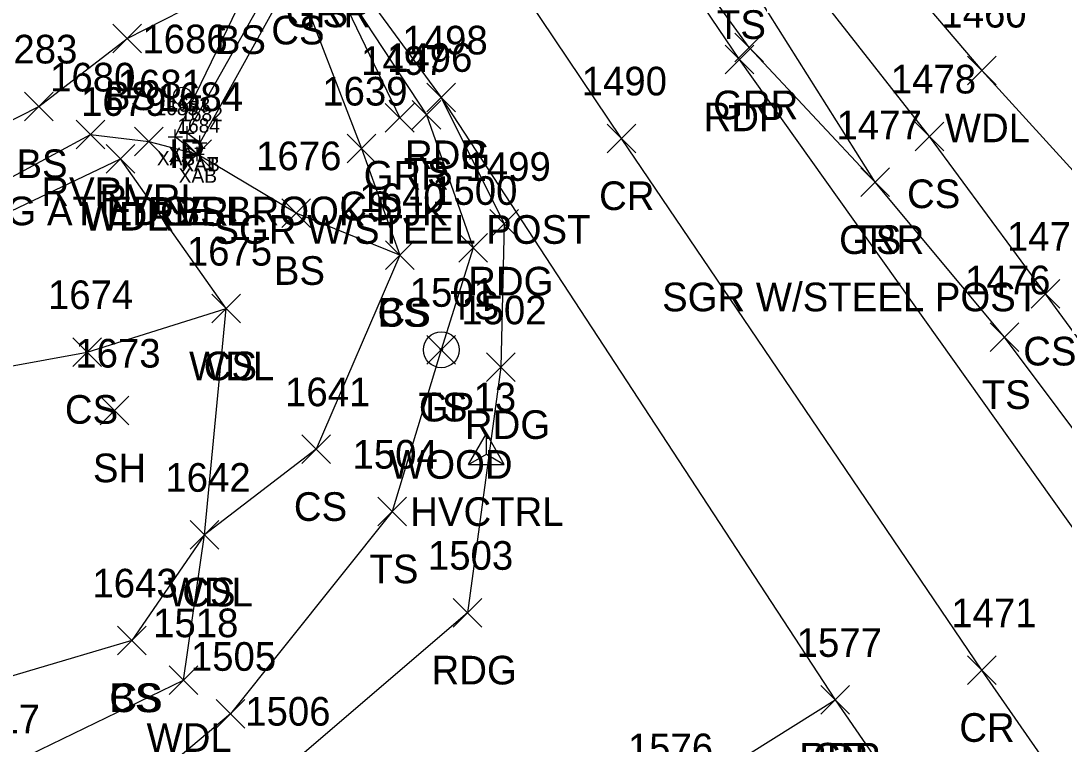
# Model space of a CAD drawing. Extents: x 1501299 to 1502485, y 381423 to 383765.
# Drawn here: x 1501597.6 to 1501670.4, y 383226.1 to 383276.5 of the extents above; entities that cross this region are included whole.
import ezdxf

# ---------------------------------------------------------------- set-up
doc = ezdxf.new("R2010")
doc.units = 0
for name, color, linetype in [('B_A', 7, 'Continuous'), ('B_I', 7, 'Continuous'), ('B_TIC', 7, 'Continuous'), ('BSUBM', 7, 'Continuous'), ('C_A', 7, 'Continuous'), ('C_I', 7, 'Continuous'), ('CPSM', 7, 'Continuous'), ('L_A', 7, 'Continuous'), ('L_C', 7, 'Continuous'), ('L_I', 7, 'Continuous'), ('L_TIC', 7, 'Continuous'), ('LAWA', 7, 'Continuous'), ('LAWE', 7, 'Continuous'), ('LELB', 7, 'Continuous'), ('M_A', 7, 'Continuous'), ('M_C', 7, 'Continuous'), ('M_I', 7, 'Continuous'), ('MPIR', 7, 'Continuous'), ('P_A', 7, 'Continuous'), ('P_I', 7, 'Continuous'), ('P_TIC', 7, 'Continuous'), ('PET', 7, 'Continuous'), ('PEU', 7, 'Continuous'), ('PRC', 7, 'Continuous'), ('R_A', 7, 'Continuous'), ('R_C', 7, 'Continuous'), ('R_I', 7, 'Continuous'), ('R_TIC', 7, 'Continuous'), ('RGP', 7, 'Continuous'), ('RGR', 7, 'Continuous')]:
    doc.layers.add(name, color=color, linetype=linetype)

msp = doc.modelspace()

# ---------------------------------------------------------------- linework, layer by layer
at = {"layer": 'B_TIC'}
for p, q in [((1501608.386, 383268.462), (1501608.461, 383268.462)), ((1501609.222, 383268.708), (1501609.297, 383268.708)), ((1501610.102, 383268.035), (1501610.177, 383268.035)), ((1501610.102, 383268.035), (1501610.177, 383268.035)), ((1501609.908, 383267.245), (1501609.984, 383267.245))]:
    msp.add_line(p, q, dxfattribs=at)
for points in [[(1501609.218, 383268.208), (1501609.218, 383269.208)], [(1501607.882, 383268.462), (1501608.882, 383268.462)], [(1501608.382, 383267.962), (1501608.382, 383268.962)], [(1501608.718, 383268.708), (1501609.718, 383268.708)], [(1501610.098, 383267.535), (1501610.098, 383268.535)], [(1501610.098, 383267.535), (1501610.098, 383268.535)], [(1501609.598, 383268.035), (1501610.598, 383268.035)], [(1501609.598, 383268.035), (1501610.598, 383268.035)], [(1501609.905, 383266.745), (1501609.905, 383267.745)], [(1501609.405, 383267.245), (1501610.405, 383267.245)]]:
    msp.add_lwpolyline(points, dxfattribs=at)
at = {"layer": 'BSUBM'}
for points in [[(1501610.098, 383268.035), (1501609.905, 383267.245), (1501608.382, 383268.462), (1501613.451, 383278.934), (1501614.534, 383280.635), (1501624.293, 383289.139), (1501630.288, 383293.913), (1501635.348, 383298.565), (1501649.431, 383296.917), (1501649.596, 383294.923)], [(1501617.009, 383280.262), (1501616.648, 383279.899), (1501610.098, 383268.035), (1501609.218, 383268.708), (1501615.801, 383280.376)]]:
    msp.add_lwpolyline(points, dxfattribs=at)
at = {"layer": 'CPSM'}
for p, q in [((1501628.837, 383245.579), (1501630.087, 383247.744)), ((1501631.337, 383245.579), (1501630.087, 383247.744)), ((1501630.087, 383246.3), (1501630.087, 383247.744)), ((1501628.837, 383245.579), (1501630.087, 383246.3)), ((1501630.087, 383246.3), (1501630.087, 383246.3)), ((1501630.087, 383246.3), (1501631.337, 383245.579)), ((1501628.837, 383245.579), (1501631.337, 383245.579))]:
    msp.add_line(p, q, dxfattribs=at)
at = {"layer": 'L_TIC'}
for points in [[(1501604.035, 383274.317), (1501606.035, 383276.317)], [(1501606.035, 383274.317), (1501604.035, 383276.317)], [(1501663.652, 383272.077), (1501665.652, 383274.077)], [(1501665.652, 383272.077), (1501663.652, 383274.077)], [(1501597.871, 383269.571), (1501599.871, 383271.571)], [(1501599.871, 383269.571), (1501597.871, 383271.571)], [(1501624.909, 383268.987), (1501626.909, 383270.987)], [(1501626.909, 383268.987), (1501624.909, 383270.987)], [(1501601.485, 383267.617), (1501603.485, 383269.617)], [(1501603.485, 383267.617), (1501601.485, 383269.617)], [(1501605.539, 383267.133), (1501607.539, 383269.133)], [(1501607.539, 383267.133), (1501605.539, 383269.133)], [(1501659.991, 383267.478), (1501661.991, 383269.478)], [(1501661.991, 383267.478), (1501659.991, 383269.478)], [(1501620.389, 383266.635), (1501622.389, 383268.635)], [(1501622.389, 383266.635), (1501620.389, 383268.635)], [(1501603.566, 383265.915), (1501605.566, 383267.915)], [(1501605.566, 383265.915), (1501603.566, 383267.915)], [(1501603.566, 383265.915), (1501605.566, 383267.915)], [(1501605.566, 383265.915), (1501603.566, 383267.915)], [(1501608.905, 383266.245), (1501610.905, 383268.245)], [(1501610.905, 383266.245), (1501608.905, 383268.245)], [(1501608.905, 383266.245), (1501610.905, 383268.245)], [(1501610.905, 383266.245), (1501608.905, 383268.245)], [(1501656.204, 383264.279), (1501658.204, 383266.279)], [(1501658.204, 383264.279), (1501656.204, 383266.279)], [(1501615.825, 383262.123), (1501617.825, 383264.123)], [(1501617.825, 383262.123), (1501615.825, 383264.123)], [(1501623.053, 383259.203), (1501625.053, 383261.203)], [(1501625.053, 383259.203), (1501623.053, 383261.203)], [(1501623.053, 383259.203), (1501625.053, 383261.203)], [(1501625.053, 383259.203), (1501623.053, 383261.203)], [(1501628.163, 383259.706), (1501630.163, 383261.706)], [(1501630.163, 383259.706), (1501628.163, 383261.706)], [(1501668.093, 383256.5), (1501670.093, 383258.5)], [(1501670.093, 383256.5), (1501668.093, 383258.5)], [(1501610.935, 383255.467), (1501612.935, 383257.467)], [(1501612.935, 383255.467), (1501610.935, 383257.467)], [(1501610.935, 383255.467), (1501612.935, 383257.467)], [(1501612.935, 383255.467), (1501610.935, 383257.467)], [(1501665.231, 383253.465), (1501667.231, 383255.465)], [(1501667.231, 383253.465), (1501665.231, 383255.465)], [(1501625.947, 383252.594), (1501627.947, 383254.594)], [(1501627.947, 383252.594), (1501625.947, 383254.594)], [(1501601.248, 383252.433), (1501603.248, 383254.433)], [(1501603.248, 383252.433), (1501601.248, 383254.433)], [(1501603.156, 383248.352), (1501605.156, 383250.352)], [(1501605.156, 383248.352), (1501603.156, 383250.352)], [(1501617.219, 383245.655), (1501619.219, 383247.655)], [(1501619.219, 383245.655), (1501617.219, 383247.655)], [(1501622.522, 383241.303), (1501624.522, 383243.303)], [(1501624.522, 383241.303), (1501622.522, 383243.303)], [(1501609.438, 383239.687), (1501611.438, 383241.687)], [(1501611.438, 383239.687), (1501609.438, 383241.687)], [(1501609.438, 383239.687), (1501611.438, 383241.687)], [(1501611.438, 383239.687), (1501609.438, 383241.687)], [(1501604.349, 383232.312), (1501606.349, 383234.312)], [(1501606.349, 383232.312), (1501604.349, 383234.312)], [(1501604.349, 383232.312), (1501606.349, 383234.312)], [(1501606.349, 383232.312), (1501604.349, 383234.312)], [(1501607.969, 383229.539), (1501609.969, 383231.539)], [(1501609.969, 383229.539), (1501607.969, 383231.539)], [(1501611.249, 383227.196), (1501613.249, 383229.196)], [(1501613.249, 383227.196), (1501611.249, 383229.196)]]:
    msp.add_lwpolyline(points, dxfattribs=at)
at = {"layer": 'LAWA'}
for points in [[(1501779.978, 383346.811), (1501771.128, 383336.509), (1501763.603, 383335.595), (1501745.623, 383331.34), (1501736.099, 383321.476), (1501724.597, 383316.37), (1501714.925, 383312.283), (1501706.399, 383305.205), (1501697.057, 383304.744), (1501686.727, 383299.314), (1501680.172, 383293.143), (1501673.639, 383291.799), (1501663.46, 383290.945), (1501650.482, 383288.163), (1501656.051, 383283.209), (1501664.652, 383273.077), (1501676.933, 383259.602)], [(1501523.121, 383213.314), (1501532.426, 383219.38), (1501535.216, 383227.124), (1501552.763, 383237.535), (1501565.994, 383247.177), (1501582.963, 383255.302), (1501593.872, 383261.815), (1501604.566, 383266.915)], [(1501528.627, 383177.649), (1501552.889, 383189.247), (1501565.057, 383199.711), (1501579.739, 383213.943), (1501595.135, 383223.841), (1501608.969, 383230.539), (1501610.438, 383240.687), (1501611.935, 383256.467), (1501604.566, 383266.915)]]:
    msp.add_lwpolyline(points, dxfattribs=at)
at = {"layer": 'LAWE'}
msp.add_lwpolyline([(1501505.158, 383203.166), (1501520.7, 383214.779), (1501528.923, 383219.093), (1501532.525, 383227.492), (1501551.851, 383239.1), (1501563.534, 383248.346), (1501581.909, 383257.47), (1501592.134, 383263.024), (1501602.485, 383268.617), (1501606.539, 383268.133), (1501609.905, 383267.245)], dxfattribs=at)
at = {"layer": 'LELB'}
for points in [[(1501590.761, 383266.457), (1501598.871, 383270.571), (1501605.035, 383275.317), (1501612.707, 383279.234), (1501613.789, 383281.85), (1501615.914, 383283.693), (1501614.455, 383284.683), (1501622.35, 383292.222), (1501627.416, 383296.435), (1501634.13, 383302.054), (1501643.772, 383300.983), (1501650.033, 383300.072), (1501651.493, 383297.792), (1501662.757, 383297.227), (1501671.557, 383298.422), (1501684.76, 383303.845), (1501698.893, 383313.194), (1501704.538, 383312.156), (1501711.847, 383316.203), (1501724.827, 383323.61), (1501744.215, 383336.813), (1501764.443, 383344.5)], [(1501740.606, 383142.674), (1501732.682, 383153.534), (1501723.163, 383169.564), (1501715.733, 383180.538), (1501695.363, 383208.817), (1501677.401, 383239.568), (1501666.231, 383254.465), (1501657.204, 383265.279), (1501647.762, 383280.285), (1501635.957, 383296.227)], [(1501736.699, 383153.056), (1501732.682, 383153.534), (1501726.373, 383172.274), (1501718.918, 383183.465), (1501700.045, 383211.098), (1501680.296, 383242.203), (1501669.093, 383257.5), (1501660.991, 383268.478), (1501649.565, 383283.093), (1501640.692, 383295.782)], [(1501619.162, 383281.8), (1501618.614, 383281.102), (1501625.909, 383269.987), (1501629.163, 383260.706), (1501626.947, 383253.594), (1501623.522, 383242.303), (1501612.249, 383228.196), (1501584.091, 383204.532), (1501565.556, 383192.677), (1501531.011, 383172.484)], [(1501616.648, 383279.899), (1501621.389, 383267.635), (1501624.053, 383260.203), (1501618.219, 383246.655), (1501610.438, 383240.687), (1501605.349, 383233.312)], [(1501624.053, 383260.203), (1501616.825, 383263.123), (1501609.905, 383267.245)], [(1501535.216, 383227.124), (1501558.161, 383232.007), (1501574.325, 383240.882), (1501582.487, 383249.817), (1501602.248, 383253.433), (1501611.935, 383256.467)], [(1501605.349, 383233.312), (1501590.603, 383228.948), (1501573.553, 383221.004), (1501565.086, 383213.343), (1501549.824, 383204.977), (1501532.49, 383198.66), (1501516.236, 383190.974)]]:
    msp.add_lwpolyline(points, dxfattribs=at)
at = {"layer": 'MPIR'}
for radius in [0.625, 0.0833]:
    msp.add_circle((1501608.89, 383271.282), radius, dxfattribs=at)
at = {"layer": 'P_TIC'}
for points in [[(1501646.754, 383272.845), (1501648.754, 383274.845)], [(1501648.754, 383272.845), (1501646.754, 383274.845)], [(1501625.926, 383270.201), (1501627.926, 383272.201)], [(1501627.926, 383270.201), (1501625.926, 383272.201)], [(1501625.926, 383270.201), (1501627.926, 383272.201)], [(1501627.926, 383270.201), (1501625.926, 383272.201)], [(1501638.517, 383267.342), (1501640.517, 383269.342)], [(1501640.517, 383267.342), (1501638.517, 383269.342)], [(1501630.334, 383261.382), (1501632.334, 383263.382)], [(1501632.334, 383261.382), (1501630.334, 383263.382)], [(1501630.108, 383251.373), (1501632.108, 383253.373)], [(1501632.108, 383251.373), (1501630.108, 383253.373)], [(1501627.782, 383234.244), (1501629.782, 383236.244)], [(1501629.782, 383234.244), (1501627.782, 383236.244)], [(1501663.644, 383230.239), (1501665.644, 383232.239)], [(1501665.644, 383230.239), (1501663.644, 383232.239)], [(1501653.425, 383228.168), (1501655.425, 383230.168)], [(1501655.425, 383228.168), (1501653.425, 383230.168)], [(1501653.425, 383228.168), (1501655.425, 383230.168)], [(1501655.425, 383228.168), (1501653.425, 383230.168)]]:
    msp.add_lwpolyline(points, dxfattribs=at)
at = {"layer": 'PET'}
msp.add_lwpolyline([(1501787.994, 383066.094), (1501768.484, 383096.751), (1501754.41, 383116.891), (1501736.241, 383144.717), (1501720.749, 383167.971), (1501712.594, 383179.719), (1501694.383, 383207.646), (1501673.597, 383237.523), (1501647.754, 383273.845), (1501633.679, 383294.635), (1501626.393, 383287.881), (1501619.162, 383281.8), (1501626.926, 383271.201), (1501654.425, 383229.168), (1501675.697, 383198.288), (1501696.699, 383166.339)], dxfattribs=at)
at = {"layer": 'PEU'}
msp.add_lwpolyline([(1501626.926, 383271.201), (1501631.334, 383262.382), (1501631.108, 383252.373), (1501628.782, 383235.244), (1501616.096, 383224.369), (1501585.575, 383201.963), (1501565.972, 383189.419), (1501531.444, 383171.521)], dxfattribs=at)
at = {"layer": 'PRC'}
for points in [[(1501960.612, 382718.648), (1501950.96, 382750.482), (1501934.965, 382791.852), (1501913.074, 382836.935), (1501889.309, 382881.383), (1501879.244, 382899.507), (1501856.391, 382940.32), (1501839.674, 382966.998), (1501816.055, 383004.313), (1501794.783, 383036.247), (1501769.812, 383075.158), (1501745.791, 383111.558), (1501729.435, 383136.001), (1501711.236, 383163.535), (1501694.816, 383188.199), (1501683.547, 383204.004), (1501664.644, 383231.239), (1501639.517, 383268.342), (1501626.393, 383287.881)], [(1501538.389, 383162.062), (1501572.089, 383180.105), (1501595.76, 383192.822), (1501620.625, 383207.907), (1501642.704, 383221.815), (1501654.425, 383229.168)]]:
    msp.add_lwpolyline(points, dxfattribs=at)
at = {"layer": 'R_TIC'}
for points in [[(1501647.418, 383273.675), (1501649.418, 383275.675)], [(1501649.418, 383273.675), (1501647.418, 383275.675)], [(1501623.041, 383268.773), (1501625.041, 383270.773)], [(1501625.041, 383268.773), (1501623.041, 383270.773)], [(1501656.204, 383264.279), (1501658.204, 383266.279)], [(1501658.204, 383264.279), (1501656.204, 383266.279)]]:
    msp.add_lwpolyline(points, dxfattribs=at)
at = {"layer": 'RGP'}
msp.add_line((1501626.947, 383253.594), (1501626.947, 383253.594), dxfattribs=at)
for radius in [1.25, 0.0833]:
    msp.add_circle((1501626.947, 383253.594), radius, dxfattribs=at)
at = {"layer": 'RGR'}
for points in [[(1501657.204, 383265.279), (1501648.418, 383274.675), (1501633.858, 383294.779)], [(1501618.614, 383281.102), (1501624.041, 383269.773)]]:
    msp.add_lwpolyline(points, dxfattribs=at)

# ---------------------------------------------------------------- texts
at = {"layer": 'B_A'}
for s, p in [('XAT', (1501607.923, 383266.708)), ('XAB', (1501607.103, 383266.462)), ('XAT', (1501608.803, 383266.035)), ('XAB', (1501608.819, 383266.035)), ('XAB', (1501608.625, 383265.245))]:
    msp.add_text(s, height=1, dxfattribs=at).set_placement(p)
at = {"layer": 'B_I'}
for s, p in [('1685', (1501607.012, 383269.962)), ('1683', (1501607.848, 383270.208)), ('1682', (1501608.728, 383269.535)), ('1682', (1501608.728, 383269.535)), ('1684', (1501608.535, 383268.745))]:
    msp.add_text(s, height=1, dxfattribs=at).set_placement(p)
at = {"layer": 'C_A'}
msp.add_text('HVCTRL', height=2, dxfattribs=at).set_placement((1501624.78, 383241.3))
at = {"layer": 'C_I'}
msp.add_text('13', height=2, dxfattribs=at).set_placement((1501629.19, 383249.3))
at = {"layer": 'L_A'}
for s, p in [('TS', (1501617.024, 383276.102)), ('TS', (1501646.172, 383275.285)), ('CS', (1501615.089, 383274.899)), ('BS', (1501611.148, 383274.234)), ('BS', (1501603.476, 383270.317)), ('WDL', (1501662.069, 383268.077)), ('BS', (1501597.312, 383265.571)), ('TS', (1501624.319, 383264.987)), ('RVRL', (1501599.052, 383263.617)), ('CS', (1501659.432, 383263.478)), ('RVRL', (1501603.106, 383263.133)), ('RVRL', (1501606.471, 383262.245)), ('BS', (1501608.346, 383262.245)), ('CS', (1501619.83, 383262.635)), ('WDR', (1501601.928, 383261.915)), ('WDL', (1501601.983, 383261.915)), ('TS', (1501655.614, 383260.279)), ('BS', (1501615.266, 383258.123)), ('TS', (1501627.573, 383255.706)), ('CS', (1501622.494, 383255.203)), ('BS', (1501622.494, 383255.203)), ('CS', (1501667.534, 383252.5)), ('WDL', (1501609.352, 383251.467)), ('CS', (1501610.376, 383251.467)), ('TS', (1501664.641, 383249.465)), ('CS', (1501600.689, 383248.433)), ('TS', (1501625.356, 383248.594)), ('SH', (1501602.644, 383244.352)), ('CS', (1501616.66, 383241.655)), ('TS', (1501621.931, 383237.303)), ('WDL', (1501607.855, 383235.687)), ('CS', (1501608.879, 383235.687)), ('CS', (1501603.79, 383228.312)), ('BS', (1501603.79, 383228.312)), ('WDL', (1501606.386, 383225.539))]:
    msp.add_text(s, height=2, dxfattribs=at).set_placement(p)
at = {"layer": 'L_C'}
msp.add_text('SGR W/STEEL POST', height=2, dxfattribs=at).set_placement((1501611.051, 383260.987))
at = {"layer": 'L_I'}
for s, p in [('1460', (1501661.825, 383276.077)), ('2283', (1501595.611, 383273.571)), ('1496', (1501623.161, 383272.987)), ('1680', (1501599.659, 383271.617)), ('1478', (1501658.298, 383271.478)), ('1681', (1501604.366, 383271.133)), ('1684', (1501607.165, 383270.245)), ('1684', (1501607.165, 383270.245)), ('1639', (1501618.641, 383270.635)), ('1679', (1501601.818, 383269.915)), ('1679', (1501601.818, 383269.915)), ('1477', (1501654.511, 383268.279)), ('1676', (1501614.03, 383266.123)), ('1500', (1501626.305, 383263.706)), ('1640', (1501621.226, 383263.203)), ('1640', (1501621.226, 383263.203)), ('1475', (1501666.4, 383260.5)), ('1675', (1501609.195, 383259.467)), ('1675', (1501609.195, 383259.467)), ('1476', (1501663.483, 383257.465)), ('1674', (1501599.508, 383256.433)), ('1501', (1501624.742, 383256.594)), ('1673', (1501601.416, 383252.352)), ('1641', (1501616.046, 383249.655)), ('1504', (1501620.75, 383245.303)), ('1642', (1501607.698, 383243.687)), ('1642', (1501607.698, 383243.687)), ('1643', (1501602.609, 383236.312)), ('1643', (1501602.609, 383236.312)), ('1518', (1501606.843, 383233.539)), ('1505', (1501609.477, 383231.196)), ('1517', (1501593.009, 383226.841))]:
    msp.add_text(s, height=2, dxfattribs=at).set_placement(p)
at = {"layer": 'M_A'}
msp.add_text('IP', height=2, dxfattribs=at).set_placement((1501607.938, 383266.282))
at = {"layer": 'M_C'}
msp.add_text('1/2"IP-4"ABG AT EDGE BROOK DJK ', height=2, dxfattribs=at).set_placement((1501582.529, 383262.282))
at = {"layer": 'M_I'}
msp.add_text('1686', height=2, dxfattribs=at).set_placement((1501606.095, 383274.282))
at = {"layer": 'P_A'}
for s, p in [('RDP', (1501645.242, 383268.845)), ('RDG', (1501624.414, 383266.201)), ('RDP', (1501624.414, 383266.201)), ('CR', (1501637.951, 383263.342)), ('RDG', (1501628.823, 383257.382)), ('RDG', (1501628.596, 383247.373)), ('RDG', (1501626.27, 383230.244)), ('CR', (1501663.077, 383226.239)), ('RDP', (1501651.913, 383224.168)), ('CR', (1501652.858, 383224.168))]:
    msp.add_text(s, height=2, dxfattribs=at).set_placement(p)
at = {"layer": 'P_I'}
for s, p in [('1498', (1501624.233, 383274.201)), ('1498', (1501624.233, 383274.201)), ('1490', (1501636.738, 383271.342)), ('1499', (1501628.634, 383265.382)), ('1502', (1501628.337, 383255.373)), ('1503', (1501626.011, 383238.244)), ('1471', (1501662.518, 383234.239)), ('1577', (1501651.732, 383232.168)), ('1577', (1501651.732, 383232.168)), ('1506', (1501613.269, 383227.369)), ('1576', (1501639.957, 383224.815))]:
    msp.add_text(s, height=2, dxfattribs=at).set_placement(p)
at = {"layer": 'R_A'}
for s, p in [('GRR', (1501616.102, 383276.102)), ('GRR', (1501645.906, 383269.675)), ('GRR', (1501621.529, 383264.773)), ('GRR', (1501654.692, 383260.279)), ('GP', (1501625.38, 383248.594))]:
    msp.add_text(s, height=2, dxfattribs=at).set_placement(p)
at = {"layer": 'R_C'}
for s, p in [('SGR W/STEEL POST', (1501642.346, 383256.279)), ('WOOD', (1501623.301, 383244.594))]:
    msp.add_text(s, height=2, dxfattribs=at).set_placement(p)
at = {"layer": 'R_I'}
for s, p in [('1497', (1501621.348, 383272.773)), ('1477', (1501654.511, 383268.279)), ('1501', (1501624.742, 383256.594))]:
    msp.add_text(s, height=2, dxfattribs=at).set_placement(p)

doc.saveas('drawing.dxf')
